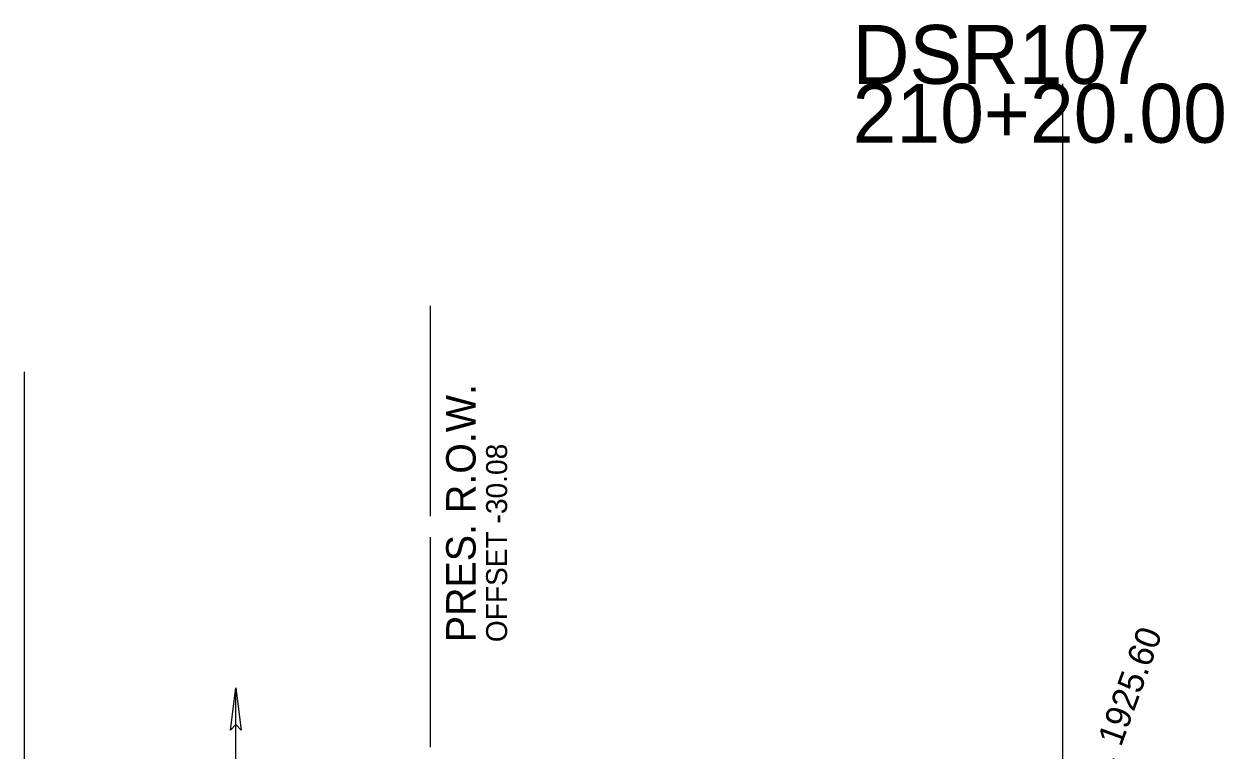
# Model space of a CAD drawing. Extents: x 1574 to 14903, y 7971 to 16537.
# Drawn here: x 14550.6 to 14607.9, y 9523.3 to 9557.8 of the extents above; entities that cross this region are included whole.
import ezdxf

# ---------------------------------------------------------------- set-up
doc = ezdxf.new("R2010")
doc.units = 0
for name, color, linetype in [('DESIGN - DRAINAGE - Special Ditches', 7, 'Continuous'), ('DESIGN - EARTHWORK - Excavation Limit Lines', 7, 'Continuous'), ('DESIGN - SHEET - Light Grid', 7, 'Continuous'), ('DESIGN - TYPICAL - Text', 7, 'Continuous'), ('SURVEY - PROPERTY - ROW Lines', 7, 'Continuous'), ('SURVEY - PROPERTY - ROW Lines Text', 7, 'Continuous')]:
    doc.layers.add(name, color=color, linetype=linetype)

msp = doc.modelspace()

# ---------------------------------------------------------------- linework, layer by layer
at = {"layer": 'DESIGN - DRAINAGE - Special Ditches'}
msp.add_line((14560.67, 9521.394), (14560.67, 9526.278), dxfattribs=at)
msp.add_lwpolyline([(14560.67, 9526.278), (14560.92, 9524.268), (14560.67, 9524.528), (14560.41, 9524.268)], close=True, dxfattribs=at)
msp.add_lwpolyline([(14560.67, 9526.278), (14560.92, 9524.268), (14560.67, 9524.528), (14560.41, 9524.268), (14560.67, 9526.278)], dxfattribs=at)
at = {"layer": 'DESIGN - EARTHWORK - Excavation Limit Lines'}
msp.add_line((14550.592, 9541.297), (14550.592, 9488.797), dxfattribs=at)
at = {"layer": 'DESIGN - SHEET - Light Grid'}
msp.add_line((14600, 9500), (14600, 9554.996), dxfattribs=at)
at = {"layer": 'SURVEY - PROPERTY - ROW Lines'}
for p, q in [((14569.918, 9534.445), (14569.918, 9544.445)), ((14569.918, 9523.445), (14569.918, 9533.445))]:
    msp.add_line(p, q, dxfattribs=at)

# ---------------------------------------------------------------- texts
at = {"layer": 'DESIGN - SHEET - Light Grid'}
for s, p in [('DSR107', (14590, 9554.996)), ('210+20.00 / 1', (14590, 9552.196))]:
    msp.add_text(s, height=2.8, dxfattribs=at).set_placement(p)
at = {"layer": 'DESIGN - TYPICAL - Text'}
msp.add_text('  FG EL. 1925.60', height=1.2, rotation=70, dxfattribs=at).set_placement((14600.564, 9517.394))
at = {"layer": 'SURVEY - PROPERTY - ROW Lines Text'}
for s, height, p in [('PRES. R.O.W.', 1.4, (14572.068, 9528.445)), ('OFFSET -30.08', 1, (14573.568, 9528.445))]:
    msp.add_text(s, height=height, rotation=90, dxfattribs=at).set_placement(p)

doc.saveas('drawing.dxf')
